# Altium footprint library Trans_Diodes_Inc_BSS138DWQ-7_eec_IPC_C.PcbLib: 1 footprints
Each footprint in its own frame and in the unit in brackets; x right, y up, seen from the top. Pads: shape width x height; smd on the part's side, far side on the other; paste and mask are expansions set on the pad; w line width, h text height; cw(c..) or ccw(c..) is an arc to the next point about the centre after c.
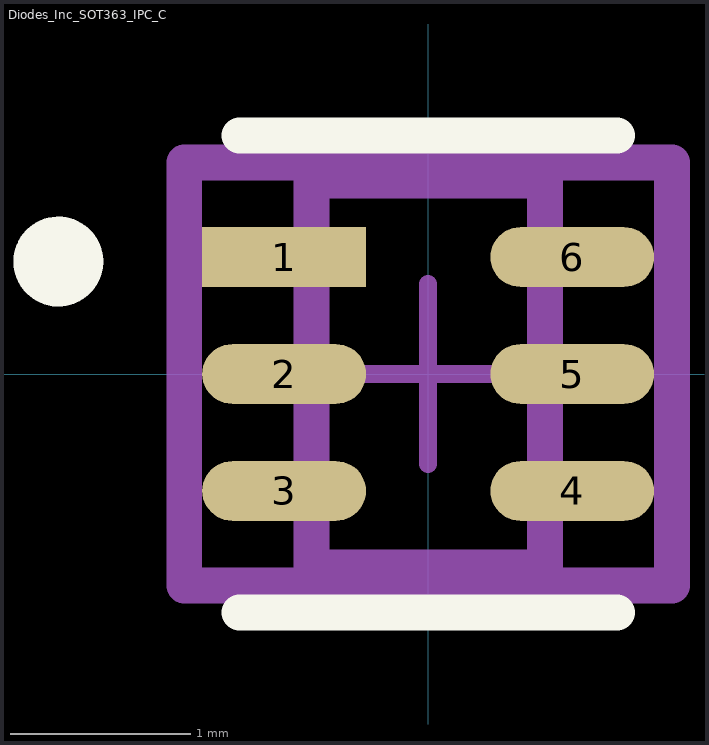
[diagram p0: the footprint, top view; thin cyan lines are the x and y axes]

## Diodes_Inc_SOT363_IPC_C [mm]
pads (6):
  rect 0.91x0.332 smd paste+0 mask+0: 1(-0.801,0.65)
  rrect100% 0.91x0.332 smd paste+0 mask+0: 2(-0.801,0) 3(-0.801,-0.65) 4(0.801,-0.65) 5(0.801,0) 6(0.801,0.65)
Top Overlay:
  circle w0.25: c-2.056,0.625 r0.125
  lines w0.2: -1.05,-1.325 1.05,-1.325 ; -1.05,1.325 1.05,1.325
Mechanical 10:
  lines w0.2: -1.356,-1.175 1.356,-1.175 1.356,1.175 -1.356,1.175 -1.356,-1.175
  text ".Designator" at 0,0.188 h1
Mechanical 12:
  lines w0.2: -0.65,-1.075 0.65,-1.075 0.65,1.075 -0.65,1.075 -0.65,-1.075
Mechanical 15:
  lines w0.1: -0.5,0 0.5,0 ; 0,-0.5 0,0.5
  lines w0.2: -1.356,-1.175 1.356,-1.175 1.356,1.175 -1.356,1.175 -1.356,-1.175
3D body "Trans_Diodes_Inc_BSS138DWQ-7_eec.STEP": height 0.25, standoff 0, extent -1.356,-1.175 1.356,1.175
